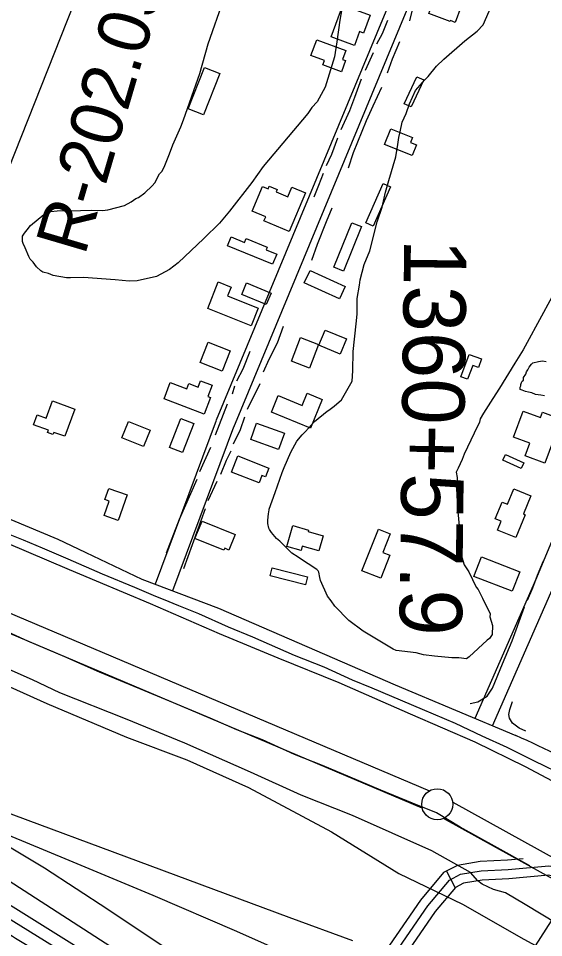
# Model space of a CAD drawing. Extents: x 3329332 to 3367211, y 631066 to 656469.
# Drawn here: x 3344512 to 3345355, y 646368 to 647841 of the extents above; entities that cross this region are included whole.
import ezdxf

# ---------------------------------------------------------------- set-up
doc = ezdxf.new("R2010")
doc.units = 0
for name, color, linetype in [('V-BLDG-OTLN', 7, 'Continuous'), ('V-FLOD-BASE', 7, 'Continuous'), ('V-LEVE-TOET', 7, 'Continuous'), ('V-RIVR-EDGE', 7, 'Continuous'), ('V-RIVR-RANG', 7, 'Continuous'), ('V-RIVR-RANG-IDEN', 7, 'Continuous'), ('V-ROAD-CNTR', 7, 'Continuous'), ('V-SITE-VEGE', 7, 'Continuous'), ('V-SURV-IDEN', 7, 'Continuous'), ('V-SURV-LINE', 7, 'Continuous'), ('V-TOPO-DPTH', 7, 'Continuous'), ('V-TOPO-MAJR', 7, 'Continuous'), ('V-TOPO-MINR', 7, 'Continuous'), ('V-TOPO-SHOR', 7, 'Continuous')]:
    doc.layers.add(name, color=color, linetype=linetype)

msp = doc.modelspace()

# ---------------------------------------------------------------- linework, layer by layer
at = {"layer": 'V-BLDG-OTLN'}
for points in [[(3345181.2, 647876.5), (3345217.1, 647862.8), (3345216.5, 647861.4), (3345222.2, 647859.2), (3345212.9, 647834.9), (3345205.4, 647837.8), (3345204.7, 647836), (3345170.7, 647849), (3345172.4, 647853.5), (3345168.1, 647855.1), (3345175.2, 647873.7), (3345179.5, 647872)], [(3345013.9, 647811.6), (3345032.8, 647862.5), (3345076.4, 647846.3), (3345065.8, 647817.8), (3345059.7, 647820.1), (3345051.4, 647797.7)], [(3344990.9, 647807), (3345037.4, 647789.7), (3345032.2, 647775.6), (3345037.2, 647773.8), (3345030.5, 647755.8), (3345000.8, 647766.9), (3345003.4, 647773.7), (3344981.6, 647781.8)], [(3344784.6, 647696.3), (3344810.7, 647762.5), (3344835.3, 647752.8), (3344809.2, 647686.6)], [(3345131.1, 647704.5), (3345151.5, 647747.8), (3345162.7, 647742.5), (3345142.2, 647699.2)], [(3345099.7, 647639.3), (3345109.7, 647664.2), (3345144.4, 647650.1), (3345141.3, 647642.4), (3345150.8, 647638.5), (3345143.9, 647621.4)], [(3344973.1, 647561.7), (3344947, 647499.4), (3344906.3, 647516.5), (3344909.1, 647523.2), (3344887.6, 647532.2), (3344904.2, 647571.7), (3344913.1, 647568), (3344914.8, 647572), (3344927.3, 647566.8), (3344925.8, 647563.2), (3344944.5, 647555.4), (3344951, 647570.9)], [(3345069.7, 647513.5), (3345097.4, 647576.6), (3345109.4, 647571.4), (3345081.7, 647508.3)], [(3345018.3, 647442.3), (3345047.2, 647513.7), (3345062.7, 647507.4), (3345033.7, 647436.1)], [(3344920.2, 647447), (3344848.1, 647476.7), (3344853.9, 647490.9), (3344875.2, 647482.1), (3344877.9, 647488.5), (3344911.6, 647474.6), (3344909.7, 647470.1), (3344926.8, 647463)], [(3344980.2, 647437.3), (3345036.6, 647411.6), (3345027.3, 647391.4), (3344971, 647417.1)], [(3344886, 647348.4), (3344816.2, 647376.1), (3344833.1, 647418.7), (3344853.6, 647410.5), (3344848, 647396.2), (3344897.2, 647376.6)], [(3344878.5, 647417.4), (3344917.9, 647400.9), (3344910.1, 647382.3), (3344870.7, 647398.8)], [(3345004.7, 647341.5), (3345038.6, 647327.5), (3345028.4, 647303), (3344994.5, 647317.1)], [(3344804.1, 647289.4), (3344817, 647322.1), (3344852.1, 647308.3), (3344839.3, 647275.6)], [(3344965.1, 647329.5), (3344993.7, 647318.3), (3344979.1, 647280.4), (3344950.5, 647291.6)], [(3345222.3, 647266.7), (3345235.6, 647302.6), (3345255.3, 647295.3), (3345250.2, 647281.5), (3345241.1, 647284.8), (3345232.9, 647262.8)], [(3344810.4, 647206.9), (3344746.1, 647231.1), (3344756, 647257.4), (3344782.6, 647247.4), (3344785.7, 647255.7), (3344800.9, 647250), (3344804.8, 647260.3), (3344823.3, 647253.4), (3344816.4, 647235), (3344820.4, 647233.5)], [(3344981.1, 647184.4), (3344918.4, 647210.1), (3344929.2, 647236.5), (3344967.7, 647220.7), (3344975.7, 647240.2), (3344999.9, 647230.3)], [(3344567, 647227.9), (3344602.9, 647215), (3344587.2, 647171.2), (3344569.2, 647177.6), (3344567.9, 647174.1), (3344559.4, 647177.2), (3344560.8, 647181), (3344536.9, 647189.6), (3344542.7, 647205.7), (3344557.2, 647200.5)], [(3344754.7, 647153.1), (3344772.8, 647199.7), (3344793.6, 647191.6), (3344775.5, 647145.1)], [(3345383.2, 647198.5), (3345357, 647128.3), (3345325.5, 647140), (3345332.9, 647160), (3345306.5, 647169.8), (3345322.1, 647211.8), (3345349.9, 647201.5), (3345352.9, 647209.7)], [(3344688.9, 647194.8), (3344723.6, 647181.2), (3344713.3, 647155.1), (3344678.6, 647168.7)], [(3344894.6, 647192.1), (3344939.1, 647176.4), (3344929.9, 647150.3), (3344885.4, 647166)], [(3344864.6, 647139.7), (3344914.3, 647120.4), (3344908.7, 647106.1), (3344902.9, 647108.3), (3344898.4, 647096.9), (3344854.5, 647113.9)], [(3345319, 647119.4), (3345289.5, 647133.1), (3345293.7, 647142.3), (3345323.3, 647128.7)], [(3344657.4, 647087.8), (3344687, 647077.3), (3344672.6, 647036.5), (3344650.1, 647044.5), (3344658.2, 647067.5), (3344651.1, 647070)], [(3345334.6, 647075.8), (3345322.5, 647046.7), (3345325.3, 647045.5), (3345310.1, 647008.8), (3345280.7, 647020.9), (3345286.6, 647035.2), (3345277.2, 647039.1), (3345288.3, 647065.9), (3345296.8, 647062.3), (3345307, 647087.2)], [(3344807, 647035.3), (3344860.2, 647013.7), (3344850.1, 646988.9), (3344843.4, 646991.7), (3344842.1, 646988.6), (3344795.6, 647007.5)], [(3344943.1, 646994.6), (3344952.8, 647028.1), (3344977.8, 647020.9), (3344977.2, 647018.7), (3345001.2, 647011.8), (3344994.2, 646987.4), (3344967.8, 646995), (3344965.8, 646988)], [(3345093.8, 646943.8), (3345063.4, 646955.8), (3345089.8, 647022.4), (3345109, 647014.8), (3345097.2, 646984.9), (3345108.3, 646980.5)], [(3345255.3, 646977.9), (3345316.8, 646954.2), (3345304.6, 646922.7), (3345243.1, 646946.4)], [(3344919.4, 646960.4), (3344976.2, 646946.2), (3344973, 646933.3), (3344916.2, 646947.5)]]:
    msp.add_lwpolyline(points, close=True, dxfattribs=at)
at = {"layer": 'V-FLOD-BASE'}
msp.add_lwpolyline([(3345332.6, 646482.7), (3345280.9, 646511.3), (3345220.9, 646544.8), (3345183.3, 646567.4), (3345144.7, 646583.1), (3345093.9, 646603.8), (3345040.8, 646626.3), (3345000, 646643.4), (3344955.3, 646661.3), (3344904, 646684.6), (3344862.9, 646700.8), (3344820.2, 646719.6), (3344761.5, 646743.8), (3344707.3, 646766.2), (3344642.8, 646793.2), (3344587.2, 646817.7), (3344527.4, 646842.7), (3344470.8, 646868.6)], dxfattribs=at)
at = {"layer": 'V-LEVE-TOET'}
for points in [[(3344492.4, 647001.1), (3344594.1, 646957.9), (3344723.7, 646903.3), (3344834.3, 646854.9)], [(3344834.3, 646854.9), (3344928.7, 646816.3), (3345026.5, 646776.4), (3345141, 646726.4), (3345244.3, 646681.5), (3345325.3, 646641.7), (3345428, 646587.3), (3345518.4, 646537.4), (3345612.2, 646490.4), (3345670.8, 646459.7), (3345693.1, 646445.6), (3345704.9, 646434.9), (3345718.8, 646422.5), (3345740.5, 646410), (3345794.7, 646381.1), (3345903, 646326.1), (3345989.5, 646277.3)], [(3346013.7, 646039.7), (3345895.4, 646104.8), (3345803.9, 646154.7), (3345690, 646221.5), (3345619.1, 646261.2), (3345512.5, 646316.8), (3345402, 646374.1), (3345325.5, 646420.5), (3345293.7, 646439.2), (3345274.2, 646444.9), (3345256.3, 646453.4), (3345249.6, 646458.5), (3345237.4, 646472), (3345175.4, 646506.6), (3345048.1, 646563.4), (3344965.9, 646595.9), (3344884.9, 646632.8), (3344779.4, 646679.4), (3344684.4, 646718.1), (3344578.8, 646760.2), (3344535.2, 646780.7), (3344440.3, 646822.7)]]:
    msp.add_lwpolyline(points, dxfattribs=at)
at = {"layer": 'V-RIVR-EDGE'}
msp.add_spline([(3345726.6, 645695.4), (3345710.3, 645706.7), (3345706, 645707.1), (3345696.7, 645709.8), (3345683.6, 645718), (3345672.7, 645726.9), (3345658.8, 645738.2), (3345648.7, 645743.7), (3345639.4, 645746), (3345632.9, 645748), (3345603.4, 645766.6), (3345581.4, 645780.7), (3345572.4, 645785), (3345555.4, 645793.9), (3345546.1, 645800.1), (3345532.6, 645806), (3345524, 645813.4), (3345515.1, 645817.3), (3345499.6, 645821.6), (3345480.7, 645830.6), (3345474.1, 645837.5), (3345464.8, 645841.1), (3345450.4, 645846.1), (3345438, 645851.6), (3345424.9, 645858.2), (3345414.4, 645862.1), (3345403.2, 645866), (3345391.6, 645870.3), (3345367.9, 645880.1), (3345352, 645885.9), (3345338.1, 645891), (3345321.8, 645896.5), (3345300.5, 645902.7), (3345290.8, 645905.5), (3345275.7, 645907.8), (3345235.8, 645916.1), (3345209, 645924.7), (3345182.3, 645936.4), (3345156.4, 645950.4), (3345125.4, 645971), (3345109.5, 645981.9), (3345099.8, 645991.7), (3345083.6, 646002.6), (3345079.7, 646004.1), (3345072, 646007.6), (3345058.4, 646015.4), (3345047.2, 646021.6), (3345036.7, 646027.5), (3345031.3, 646033.3), (3345026.7, 646039.1), (3345021.2, 646043.8), (3344994.5, 646058.6), (3344983.7, 646064.9), (3344981.8, 646070.7), (3344976.7, 646076.1), (3344962, 646083.1), (3344939.9, 646096.8), (3344923.3, 646108), (3344901.6, 646122.8), (3344889.6, 646131.4), (3344869.1, 646144.2), (3344864.4, 646148.5), (3344847.8, 646159.4), (3344817.2, 646179.7), (3344808.7, 646184.3), (3344794.7, 646192.1), (3344773.1, 646202.7), (3344760.3, 646211.6), (3344744.4, 646224.1), (3344736.7, 646231.4), (3344732.8, 646234.9), (3344710.7, 646245.9), (3344691.8, 646256.8), (3344677.4, 646263.4), (3344663.5, 646270.4), (3344646.4, 646279.8), (3344631.7, 646288.3), (3344630.6, 646291), (3344624, 646294.9), (3344606.2, 646307.4), (3344563.2, 646333.1), (3344534.5, 646350.2), (3344492.3, 646375.9), (3344459, 646398.5), (3344451.3, 646403.9), (3344437.7, 646412.5), (3344413.7, 646427.7), (3344366.5, 646453.4), (3344331.6, 646475.2), (3344310, 646488.1), (3344300.7, 646492), (3344285.5, 646499), (3344268.5, 646506.8), (3344249.9, 646518.8), (3344243.7, 646523.9), (3344230.2, 646531.3), (3344213.9, 646541), (3344196.9, 646551.5), (3344176, 646564.4), (3344151.2, 646577.3), (3344146.9, 646581.5), (3344142.3, 646583.9), (3344134.5, 646585.1), (3344108.6, 646594.8), (3344078.7, 646610.4), (3344072.1, 646611.2), (3344057.8, 646616.7), (3344035, 646628.3), (3344016.8, 646636.5), (3343997, 646644), (3343970.7, 646656.8), (3343940.1, 646674), (3343908.3, 646692.6), (3343880.4, 646708.2), (3343858, 646717.6), (3343833.5, 646728.5), (3343826.2, 646734.3), (3343820, 646736.7), (3343805.3, 646741.8), (3343796, 646746.1), (3343784.7, 646753.8), (3343774.3, 646760.8), (3343754.5, 646769.8), (3343741, 646776.1), (3343736.3, 646780.7), (3343730.5, 646785.8), (3343725.9, 646790), (3343710.4, 646800.2), (3343695.7, 646809.9), (3343682.9, 646818.9), (3343675.9, 646822), (3343662.8, 646826.3), (3343657.7, 646828.6), (3343655.8, 646833.3), (3343653.9, 646835.6), (3343636.8, 646843.4)], degree=3, dxfattribs=at)
at = {"layer": 'V-RIVR-RANG'}
msp.add_line((3345408.3, 646459.5), (3344790.5, 645492), dxfattribs=at)
at = {"layer": 'V-ROAD-CNTR'}
msp.add_line((3345212.9, 646447.8), (3345199.1, 646474.4), dxfattribs=at)
for points in [[(3346165.1, 650423.2), (3346104, 650274.2), (3346049, 650142.5), (3345907.4, 649798.6), (3345695.5, 649289.9), (3345409.2, 648593.2), (3344829.6, 647196.9)], [(3346192.8, 650411.9), (3346131.7, 650262.8), (3346076.7, 650131), (3345935.1, 649787.1), (3345723.2, 649278.5), (3345436.9, 648581.7), (3344857.3, 647185.4)], [(3345245.2, 646719.2), (3345342.6, 646940.9), (3345531.9, 647395.7), (3345671, 647745.7), (3345827.4, 648126.6), (3345886.5, 648265.7), (3346017.4, 648601.1), (3346078.6, 648752.7)], [(3345272.6, 646707.1), (3345370.2, 646929.1), (3345559.7, 647384.3), (3345698.8, 647734.4), (3345855.1, 648115), (3345914.3, 648254.4), (3346045.2, 648590.1), (3346106.5, 648741.5)], [(3341365, 648365.6), (3341840.4, 648159.6), (3342201.6, 648010.6), (3342541.6, 647867.4), (3342842.4, 647742.5), (3343199.3, 647589.8), (3343603.1, 647418.4), (3343945, 647273.2), (3344234, 647149.2), (3344575.8, 647006.5), (3344710.2, 646942.3), (3344833.4, 646895.7), (3345116.8, 646772.8)], [(3344829.4, 647196.4), (3344731.6, 646934.1)], [(3344857.5, 647185.9), (3344759.7, 646923.6)], [(3345116.8, 646772.8), (3345310.1, 646691.7)], [(3345322, 646494), (3345296.9, 646491.6), (3345253.1, 646489.8), (3345216.5, 646483.4), (3345194.2, 646471.9), (3345157.2, 646427.6), (3345017.7, 646225)], [(3345030.1, 646216.5), (3345169.1, 646418.5), (3345203.8, 646459.9), (3345221.3, 646469), (3345254.7, 646474.8), (3345297.9, 646476.7), (3345363.1, 646482.7), (3345444.2, 646468.7), (3345551.8, 646452.2), (3345687.3, 646441.7), (3345715.1, 646444.3), (3345743.5, 646465.1)], [(3345366.8, 646466.8), (3345362.5, 646467.6), (3345298.9, 646461.7), (3345256.3, 646459.9), (3345226.2, 646454.6), (3345213.4, 646448), (3345181.1, 646409.4), (3345042.4, 646208)]]:
    msp.add_lwpolyline(points, dxfattribs=at)
msp.add_arc((3344438.6, 644743.8), 2133.9, 57.3299, 65.895, dxfattribs=at)
at = {"layer": 'V-SITE-VEGE'}
for points in [[(3345040.4, 647907.8), (3345027.9, 647838.5), (3345023.2, 647803.4), (3345019.7, 647779.6), (3345004.4, 647731.1), (3344991.5, 647707.4), (3344983.1, 647698.2), (3344976.7, 647689), (3344904.9, 647604), (3344886.8, 647578.4), (3344850.8, 647532.3), (3344835, 647512.8), (3344809.7, 647488.3), (3344768.6, 647449.6), (3344754.9, 647438.4), (3344734, 647427.3), (3344702.8, 647420.6), (3344690.3, 647419.7), (3344667.6, 647422.2), (3344616.8, 647426.1), (3344596, 647425.4), (3344589.8, 647425.5), (3344568.1, 647428.9), (3344560.9, 647432.1), (3344551.6, 647434.4), (3344548.5, 647436.5), (3344541.4, 647442.8), (3344536.3, 647450.2), (3344531.2, 647455.4), (3344529.2, 647459.6), (3344523.2, 647473.2), (3344520.2, 647480.5), (3344519.2, 647483.6), (3344519.3, 647491.9), (3344522.5, 647497.1), (3344526.7, 647502.2), (3344532, 647509.4), (3344553.1, 647526.7), (3344564.6, 647531.7), (3344574.9, 647532.5), (3344612.3, 647533), (3344629.9, 647533.7), (3344647.6, 647533.4), (3344655.9, 647534.4), (3344682.9, 647541.2), (3344693.4, 647547.2), (3344700.7, 647552.3), (3344704.9, 647554.3), (3344715.4, 647561.4), (3344727, 647572.6), (3344731.2, 647577.8), (3344738.7, 647592.2), (3344742.9, 647596.2), (3344747.2, 647605.5), (3344754.8, 647624), (3344760.2, 647638.5), (3344773.1, 647667.3), (3344777.4, 647678.7), (3344803.5, 647752.9), (3344816.7, 647800.4), (3344841.7, 647872.6)], [(3344931.6, 647003.1), (3344926.5, 647007.3), (3344918.3, 647016.8), (3344915.3, 647022), (3344914.3, 647024.1), (3344912.3, 647031.4), (3344912.4, 647033.5), (3344912.4, 647036.6), (3344913.6, 647046.9), (3344914.8, 647053.1), (3344914.8, 647054.2), (3344924.5, 647081), (3344935.4, 647113), (3344938.7, 647121.2), (3344949.4, 647145.9), (3344959, 647163.4), (3344967.5, 647173.6), (3344972.8, 647178.7), (3344987.5, 647195.1), (3345007.5, 647211.4), (3345010.6, 647213.4), (3345019, 647219.5), (3345030.6, 647229.7), (3345047.7, 647259.5), (3345049, 647276.1), (3345049.5, 647307.2), (3345054.3, 647351.7), (3345055.6, 647367.2), (3345056, 647392.1), (3345059.5, 647413.8), (3345060.6, 647422.1), (3345067.3, 647446.9), (3345075.9, 647468.5), (3345088.1, 647515), (3345095.7, 647538.8), (3345101.3, 647562.5), (3345106.7, 647581.1), (3345117.7, 647619.3), (3345121.1, 647639), (3345122.4, 647650.3), (3345124.6, 647659.6), (3345127.9, 647675.1), (3345134.4, 647688.5), (3345139.8, 647704), (3345149.5, 647725.6), (3345164.3, 647743), (3345169.6, 647748.1), (3345183.3, 647764.5), (3345194.9, 647775.7), (3345228.5, 647805.3), (3345248.5, 647820.5), (3345258, 647830.7), (3345278.5, 647879.2)], [(3345368.2, 647394.4), (3345328.7, 647321.4), (3345322.3, 647310.1), (3345308.5, 647288.5), (3345284, 647248.5), (3345273.3, 647232), (3345258.5, 647208.4), (3345253.1, 647199.2), (3345252, 647194), (3345243.4, 647176.5), (3345227.3, 647142.5), (3345224.1, 647134.3), (3345217.6, 647119.9), (3345214.4, 647113.7), (3345216.4, 647105.4), (3345215, 647087.8), (3345216.6, 647055.6), (3345221.1, 647010.9), (3345221.8, 646992.2), (3345223.7, 646977.7), (3345227.6, 646965.2), (3345234.7, 646953.7), (3345246.8, 646929.6), (3345249.8, 646925.4), (3345256.8, 646911.8), (3345268.9, 646886.7), (3345268.8, 646881.6), (3345272.7, 646868), (3345272.5, 646853.5), (3345268.3, 646847.3), (3345264.1, 646844.3), (3345235.6, 646817.8), (3345231.4, 646814.7), (3345219, 646816), (3345207.6, 646816.2), (3345179.6, 646818.7), (3345162.1, 646821), (3345150.7, 646824.3), (3345118.6, 646827.9), (3345113.5, 646830.1), (3345065.2, 646858.9), (3345042.6, 646875.8), (3345020.2, 646899), (3345014.1, 646907.4), (3345008, 646914.8), (3344997, 646939.8), (3344996, 646945), (3344994.1, 646953.3), (3344993.1, 646955.4), (3344991, 646957.5), (3344963.3, 646975.6), (3344961.3, 646977.7), (3344951, 646984.1), (3344931.6, 647003.1)], [(3345356.1, 647236.2), (3345350.5, 647237.3), (3345341.6, 647238.5), (3345336, 647240.8), (3345330.4, 647241.9), (3345325.9, 647243.1), (3345320.3, 647245.4), (3345317, 647246.5), (3345317, 647249.9), (3345318.1, 647252.1), (3345318.1, 647254.3), (3345319.3, 647257.7), (3345320.4, 647259.9), (3345322.7, 647261), (3345322.7, 647265.5), (3345326.1, 647271.1), (3345327.2, 647274.5), (3345329.5, 647277.8), (3345331.8, 647282.3), (3345335.2, 647286.7), (3345337.4, 647289), (3345346.4, 647291.1), (3345353.1, 647292.2), (3345358.7, 647291.1)], [(3344411.8, 646808.7), (3344558.1, 646742.9), (3344685.8, 646689.1), (3344782.8, 646652.6), (3344881.3, 646608.4), (3345014.5, 646537.2), (3345122.8, 646470.1), (3345224.8, 646421.2), (3345323.3, 646365.3), (3345431.6, 646306.1), (3345548.6, 646242.9), (3345633.3, 646202), (3345697.2, 646179.5), (3345726.8, 646171), (3345824.9, 646111.4), (3345960.3, 646026.8), (3346101.3, 645943.7), (3346302.6, 645834.1)], [(3344757.3, 646344.9), (3344655.8, 646412.8), (3344554.6, 646479.1), (3344414.8, 646562.2)]]:
    msp.add_lwpolyline(points, dxfattribs=at)
at = {"layer": 'V-SURV-LINE'}
for points in [[(3341255.1, 648261.7), (3345171.7, 646602.9)], [(3345160, 646575.3), (3341243.4, 648234.1)], [(3345209, 646584.8), (3347329.4, 645411.7)], [(3347314.9, 645385.4), (3345194.5, 646558.5)]]:
    msp.add_lwpolyline(points, dxfattribs=at)
msp.add_circle((3345184.3, 646581.3), 25, dxfattribs=at)
at = {"layer": 'V-TOPO-DPTH'}
msp.add_lwpolyline([(3345335, 645897.6), (3344333.9, 646521.9)], dxfattribs=at)
at = {"layer": 'V-TOPO-MAJR'}
msp.add_lwpolyline([(3345049, 646362.4), (3344946.8, 646399.9), (3344844.7, 646437.5), (3344346.4, 646622.7)], dxfattribs=at)
at = {"layer": 'V-TOPO-MINR'}
for points in [[(3345129.7, 646258.9), (3344862.7, 646377.5), (3344728.4, 646434.9), (3344593.7, 646491.4), (3344363.2, 646586.7)], [(3347756.7, 644421.9), (3347049.8, 645031.1), (3347038.7, 645037.8), (3347027.5, 645044.2), (3347016.2, 645050.5), (3347004.9, 645056.7), (3346446.6, 645354.3), (3346423.2, 645366.9), (3346400, 645379.6), (3346376.9, 645392.5), (3346353.8, 645405.6), (3346320.3, 645424.8), (3346314.1, 645428.4), (3346307.8, 645431.9), (3346301.6, 645435.4), (3346295.3, 645438.8), (3345363.5, 645900.6), (3345357.9, 645903.2), (3345352.3, 645905.9), (3344349.1, 646553.9)], [(3345335, 645897.6), (3344333.9, 646521.9)], [(3347723.6, 644400.6), (3347007, 645000.6), (3346977, 645019.7), (3346946.5, 645038.3), (3346915.7, 645056.2), (3346884.6, 645073.7), (3346853.3, 645090.8), (3346821.9, 645107.6), (3346317.7, 645370.9), (3346302.1, 645379.1), (3346286.5, 645387.3), (3346270.9, 645395.4), (3346255.3, 645403.6), (3346189.4, 645438.3), (3346154.9, 645456.5), (3346120.4, 645475), (3345983.4, 645550.4), (3345949.1, 645569.2), (3345914.8, 645588), (3345381.3, 645858), (3345361.8, 645867.3), (3345342.3, 645876.7), (3345322.8, 645886.2), (3344355.3, 646485.4)]]:
    msp.add_lwpolyline(points, dxfattribs=at)
at = {"layer": 'V-TOPO-SHOR'}
for p, q in [((3345140.2, 647837.4), (3345145.1, 647857)), ((3345069.1, 647758), (3345082.1, 647786.5)), ((3344855.7, 647239.3), (3344859.7, 647251.9)), ((3344879.9, 647214.5), (3344900.4, 647255.8)), ((3344828.6, 647173.4), (3344848, 647223.1)), ((3344803.3, 647114.7), (3344821.2, 647153.8)), ((3344816.8, 647068.5), (3344831.3, 647099.2)), ((3344778, 646959.2), (3344812.3, 647055.6))]:
    msp.add_line(p, q, dxfattribs=at)
for points in [[(3344422.9, 647414.6), (3344664.7, 648024), (3344912.9, 648617.7), (3345032.2, 648908.2), (3345368.3, 649735.6), (3345462.5, 649962.9), (3345654.1, 650433.4)], [(3345087.5, 647800.5), (3345096.3, 647816.9), (3345104.9, 647838.2)], [(3345104.4, 647754.2), (3345112.6, 647776.2), (3345124, 647804.2)], [(3345030.1, 647663.1), (3345044, 647693.5), (3345052, 647714.7), (3345062.5, 647744.1)], [(3345042.1, 647601.4), (3345049.8, 647626.5), (3345070.8, 647677.4), (3345081.6, 647701.1), (3345095.3, 647731)], [(3345006.7, 647605.5), (3345015, 647623.7), (3345024.7, 647649.9)], [(3344986.8, 647555), (3344994.5, 647573.9), (3345001.9, 647593.2)], [(3344982.9, 647453.6), (3344992.3, 647479.3), (3345006.8, 647515.6), (3345015.6, 647537.4)], [(3344905.8, 647274.8), (3344914.9, 647294.7), (3344928.2, 647320.9), (3344937.4, 647347.7)], [(3344862.8, 647260.3), (3344873, 647279.3), (3344884.1, 647307.5)], [(3344857.5, 647158.9), (3344868.5, 647182.1), (3344875.7, 647202.2)], [(3344837, 647110.6), (3344846.1, 647133.2), (3344853.5, 647148)], [(3344749.9, 646984.6), (3344771, 647038.5), (3344799.1, 647102.7)], [(3344488, 647018.1), (3344520.1, 647005), (3344550.8, 646992.7), (3344591.6, 646974.6), (3344646.9, 646950.7), (3344698.6, 646929.6), (3344732.4, 646915.1), (3344744.6, 646910), (3344769.5, 646900), (3344801.4, 646886.9), (3344848.8, 646865.6), (3344887.7, 646849.7), (3344955, 646820.1), (3345002.2, 646801.4), (3345047.7, 646780.9), (3345079.5, 646768.1), (3345110.8, 646754.7), (3345160, 646733.7), (3345213, 646711.2), (3345255.5, 646690.8), (3345295.7, 646672.6), (3345339.8, 646650.8), (3345390.3, 646626.4)], [(3345328.9, 646908.3), (3345337.6, 646928.4), (3345345.3, 646948.8), (3345354.8, 646971.7)], [(3345237.3, 646743.1), (3345249.4, 646745.6), (3345264.5, 646754.4), (3345273, 646767.5), (3345289, 646806.4), (3345304.6, 646843.5), (3345324.3, 646897.7)], [(3345326.4, 646698.6), (3345315.5, 646703.1), (3345304.9, 646711.3), (3345299.9, 646719.2), (3345299.1, 646725.1), (3345300.8, 646733.2), (3345304.9, 646746)]]:
    msp.add_lwpolyline(points, dxfattribs=at)

# ---------------------------------------------------------------- texts
at = {"layer": 'V-RIVR-RANG-IDEN'}
msp.add_text('R-202.05', height=83, rotation=73.5877, dxfattribs=at).set_placement((3344618.9, 647459.4))
at = {"layer": 'V-SURV-IDEN'}
msp.add_text('1360+57.9', height=100, rotation=269.3041, dxfattribs=at).set_placement((3345131.3, 647487.9))

doc.saveas('drawing.dxf')
